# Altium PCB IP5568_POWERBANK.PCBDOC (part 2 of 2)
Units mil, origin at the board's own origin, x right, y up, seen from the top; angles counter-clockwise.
Board outline 4566.93 x 4566.93 mil, 4 copper layers (Top Layer, MID1, MID2, Bottom Layer), stack 38.627 mil thick; 85 components, 61 nets, 294 pads, 184 vias.
Unrouted connection lines stored in the file: 1.
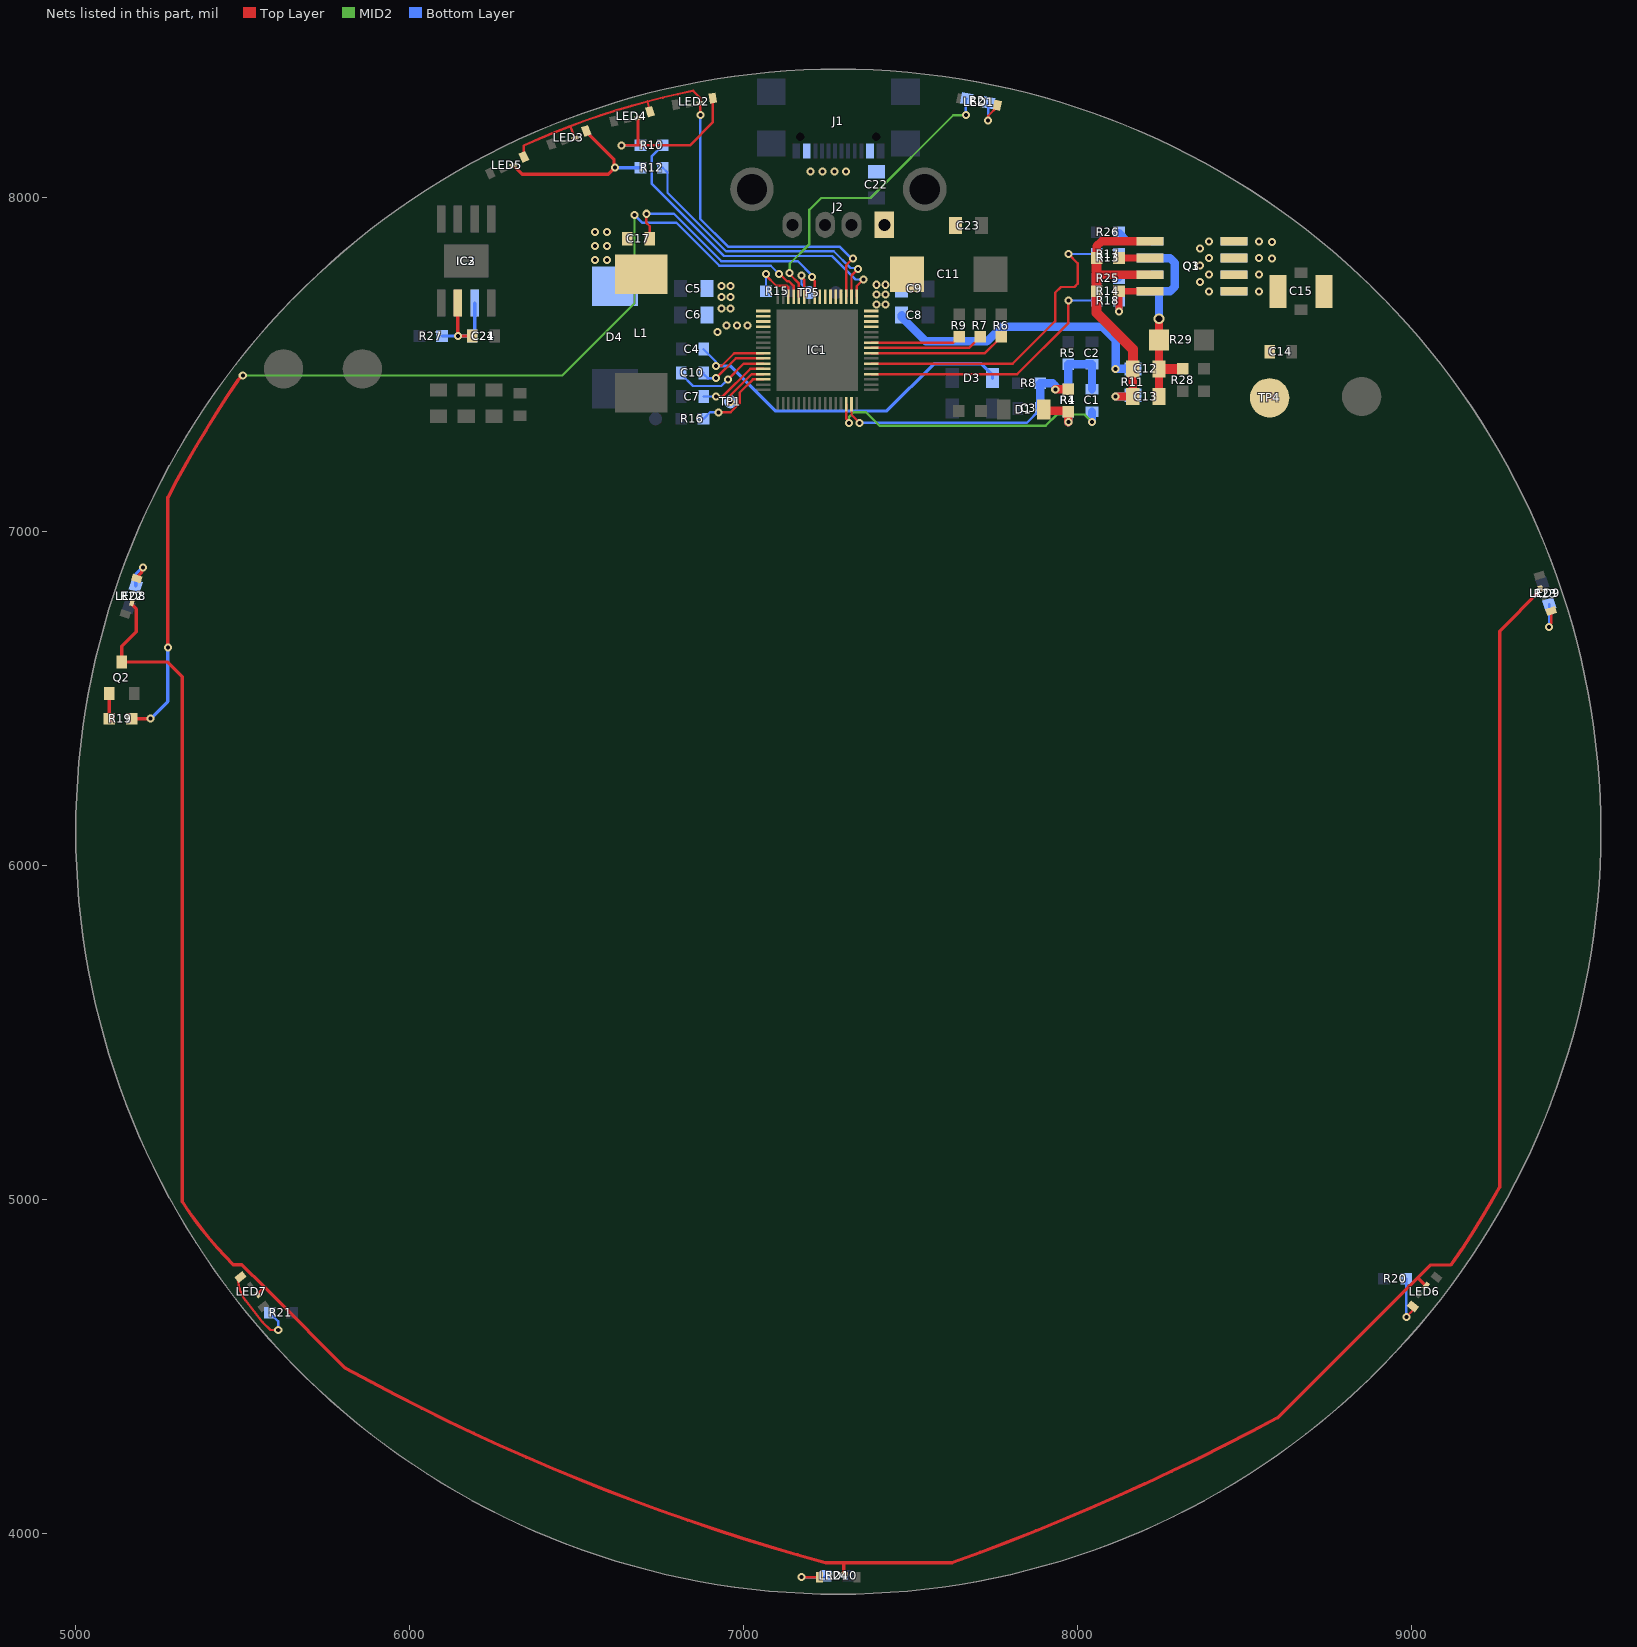
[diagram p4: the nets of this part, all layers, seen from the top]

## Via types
v1: diameter 24, hole 12, Top Layer to Bottom Layer, 166 vias
v2: diameter 32, hole 20, Top Layer to Bottom Layer, 18 vias

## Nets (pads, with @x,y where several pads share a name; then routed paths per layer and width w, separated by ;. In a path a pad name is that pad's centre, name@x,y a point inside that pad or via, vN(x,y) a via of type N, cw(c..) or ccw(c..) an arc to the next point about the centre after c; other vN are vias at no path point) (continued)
LED_G: LED6.3 LED7.3 LED8.3 LED9.3 LED10.3 Q2.3 | length 8606.9
  Top Layer w10: LED8.3@5168.42,6788.5 5168.42,6782.08 5181.1,6769.4 5181.1,6700.79 5137.8,6657.48 Q2.3@5137.8,6610.24 5275.59,6610.24 5318.9,6566.93 5318.9,4996.36 5318.9,4994.29 ccw(c6286.81,5620.98) 5471.46,4805.63 5474.36,4805.63 5497.52,4805.63 5565.64,4737.51 ; LED7.3@5544.69,4716.56 5565.64,4737.51 ; LED10.3@7300.2,3878.74 7300.2,3913.39 ; LED6.3@9043.17,4742.78 9018.96,4766.99 ; LED9.3@9387.17,6829.22 9387.17,6826.57 9263.78,6703.18 9263.78,5037.59 cw(c6837.52,6394.47) 9118.16,4804.95 9056.92,4804.95 9018.96,4766.99 ; 5565.64,4737.51 5586.59,4716.56 5805.71,4497.44 5806.41,4496.74 ccw(c8968.12,10228.09) 7244.96,3913.39 7245.89,3913.39 7300.2,3913.39 ; 7300.2,3913.39 7625.21,3913.39 ccw(c5102.66,10885.2) 8599.42,4347.46 9018.96,4766.99
NetC1_1: C1.1 C2.1 R1.1 R5.1 | length 220.5
  Bottom Layer w25: R1.1@7972.44,7427.17 R5.1@7972.44,7501.97 C2.1@8043.31,7501.97 C1.1@8043.31,7427.17
NetC7_2: C7.2 IC1.28 | length 213.4
  Top Layer w7: v1(6917.32,7405.51) 6936.89,7405.51 7019.57,7488.19 IC1.28@7059.06,7488.19
  Bottom Layer w7: C7.2@6879.92,7405.51 v1(6917.32,7405.51)
NetC10_1: C10.1 IC1.26 | length 212.2
  Top Layer w7: v1(6917.32,7460.63) 6976.38,7519.69 IC1.26@7059.06,7519.69
  Bottom Layer w7: C10.1@6879.92,7476.38 6879.92,7472.88 6892.17,7460.63 v1(6917.32,7460.63)
NetC10_2: C10.2 IC1.27 | length 292.4
  Top Layer w7: v1(6952.76,7456.69) 7000,7503.94 IC1.27@7059.06,7503.94
  Bottom Layer w7: C10.2@6812.99,7476.38 6812.99,7472.44 6848.43,7437.01 6933.07,7437.01 v1(6952.76,7456.69)
NetC12_2: C12.2 C13.2 Q3.1 Q3.3 R28.1 R29.1 | length 622
  Top Layer w25: v2(8243.52,7638.37) R29.1@8243.52,7574.8 8243.81,7574.52 8243.81,7405.8 C13.2@8244.09,7405.51 ; C12.2@8244.09,7488.19 C12.2@8247.05,7485.24
  Top Layer w30: C12.2@8244.09,7488.19 R28.1@8314.96,7488.19
  Bottom Layer w25: Q3.1@8216.77,7720.28 Q3.1@8243.23,7720.28 ; Q3.3@8216.77,7820.28 8217.07,7819.98 8276.69,7819.98 8291.34,7805.34 8291.34,7734.92 8276.69,7720.28 Q3.1@8243.23,7720.28 ; v2(8243.52,7638.37) 8243.52,7719.98 Q3.1@8243.23,7720.28
NetC14_2: C14.2 Q1.5 Q1.6 Q3.5 Q3.6 TP4.1
  other v1: 8393.7,7720.28 8366.14,7748.03 8393.7,7770.28 8366.14,7798.03 8393.7,7820.28 8366.14,7848.03 8393.7,7870.28
NetC15_A: C15.A C15.B Q1.7 Q1.8 Q3.7 Q3.8
  other v1: 8542.83,7720.28 8542.83,7770.28 8582.68,7818.9 8542.83,7820.28 8582.68,7868.9 8542.83,7870.28
NetC17_1: C17.1 IC1.9 | length 718
  Top Layer w7: v1(6708.66,7952.76) 6708.66,7925.2 6718.5,7915.35 C17.1@6718.5,7877.95 ; v1(7204.72,7763.78) 7204.72,7759.18 7212.6,7751.31 IC1.9@7212.6,7704.72
  Bottom Layer w7: v1(6708.66,7952.76) 6791.34,7952.76 6933.07,7811.02 7161.74,7811.02 7204.72,7768.04 v1(7204.72,7763.78)
NetC17_2: C17.2 D4.K IC1.4 IC1.5 IC1.6 IC1.7 IC1.8 L1.1
  other v1: 6555.12,7814.96 6590.55,7814.96 6555.12,7856.3 6590.55,7856.3 6555.12,7897.64 6590.55,7897.64
NetC21_1: C21.1 C24.1 IC2.6 IC3.6 R27.1 | length 333.6
  Top Layer w10: IC3.6@6144.29,7685.28 v1(6144.29,7586.61) C24.1@6187.01,7586.61
  Bottom Layer w10: R27.1@6096.46,7586.61 v1(6144.29,7586.61) C21.1@6187.01,7586.61 6194.29,7593.9 IC2.6@6194.29,7685.28
NetD1_K: D1.K R1.2 R4.2 | length 139.3
  Top Layer w25: D1.K@7898.58,7366.14 7901.54,7363.19 7969.49,7363.19 R4.2@7972.44,7360.24 v1(7972.44,7328.74)
  Bottom Layer w25: v1(7972.44,7328.74) R1.2@7972.44,7360.24
NetIC1_1: IC1.1 R10.1 | length 940.3
  Top Layer w7: IC1.1@7338.58,7704.72 7338.58,7736.22 v1(7358.27,7755.91)
  Bottom Layer w7: R10.1@6757.87,8157.48 6724.41,8124.02 6724.41,8043.31 6941.39,7826.33 7264.11,7826.33 7334.53,7755.91 v1(7358.27,7755.91)
NetIC1_2: IC1.2 R12.1 | length 836.7
  Top Layer w7: IC1.2@7322.83,7704.72 7322.83,7767.72 v1(7342.52,7787.4)
  Bottom Layer w7: R12.1@6757.87,8090.55 6771.87,8076.55 6771.87,8015.64 6947.18,7840.33 7269.91,7840.33 7320.02,7790.22 7339.7,7790.22 v1(7342.52,7787.4)
NetIC1_3: IC1.3 LED2.2 LED3.2 LED4.1 LED5.1 | length 1658.7
  Top Layer w7: LED5.1@6341.76,8123.02 6341.76,8157.04 cw(c7297.89,6061.85) 6480.86,8215.1 ; LED3.2@6495.1,8179.01 6480.86,8215.1 ; LED4.1@6719.55,8258.61 6712.14,8289.16 ; v1(6870.08,8248.03) 6869.72,8248.39 6869.72,8283.11 LED2.2@6870.08,8283.46 6870.08,8299.21 6851.29,8318 6848.64,8320.65 ccw(c7297.89,6061.85) 6712.14,8289.16 ; IC1.3@7307.09,7704.72 7307.09,7799.21 v1(7326.77,7818.9) ; 6480.86,8215.1 cw(c7297.89,6061.85) 6712.14,8289.16
  Bottom Layer w7: v1(6870.08,8248.03) 6870.08,7937.24 6952.98,7854.33 7287.05,7854.33 7322.49,7818.9 v1(7326.77,7818.9)
NetIC1_11: IC1.11 TP5.1 | length 127.2
  Top Layer w7: v1(7173.23,7767.72) 7173.23,7763.12 7181.1,7755.24 IC1.11@7181.1,7704.72
  Bottom Layer w7: v1(7173.23,7767.72) 7173.23,7742.11 7196.85,7718.48 TP5.1@7196.85,7716.54
NetIC1_12: IC1.12 R2.1 | length 931.8
  Top Layer w7: v1(7137.8,7775.59) 7137.8,7771.33 7165.35,7743.77 IC1.12@7165.35,7704.72
  MID2 w7: v1(7137.8,7775.59) 7137.8,7803.15 7196.85,7862.2 7196.85,7964.57 7232.28,8000 7379.86,8000 7627.89,8248.03 v1(7665.35,8248.03)
  Bottom Layer w7: v1(7665.35,8248.03) 7665.35,8294.67 R2.1@7667.83,8297.15
NetIC1_13: IC1.13 R19.2 | length 3293.1
  Top Layer w7: v1(7106.3,7771.65) 7108.87,7771.65 7129.64,7750.88 7135.49,7750.88 7149.61,7736.76 IC1.13@7149.61,7704.72
  Top Layer w10: R19.2@5167.32,6440.94 v1(5224.41,6440.94) ; v1(5275.59,6653.54) 5275.59,7103.53 cw(c8474.13,5425.33) 5485.72,7454.22 v1(5500,7468.5)
  MID2 w7: v1(5500,7468.5) 6456.69,7468.5 6673.23,7685.04 v1(6673.23,7948.82)
  Bottom Layer w7: v1(6673.23,7948.82) 6695.91,7926.14 6798.15,7926.14 6927.27,7797.02 7080.93,7797.02 v1(7106.3,7771.65)
  Bottom Layer w10: v1(5224.41,6440.94) 5275.59,6492.13 v1(5275.59,6653.54)
NetIC1_29: IC1.29 TP1.1 | length 144.2
  Top Layer w7: v1(6960.63,7389.76) 6960.63,7409.45 7023.62,7472.44 IC1.29@7059.06,7472.44
NetIC1_56: IC1.56 R6.1 | length 410.1
  Top Layer w7: IC1.56@7381.89,7535.43 7722.44,7535.43 R6.1@7771.65,7584.65
NetIC1_57: IC1.57 R7.1 | length 340.6
  Top Layer w7: IC1.57@7381.89,7551.18 7675.2,7551.18 R7.1@7708.66,7584.65
NetIC1_58: IC1.58 R9.1 | length 271.1
  Top Layer w7: IC1.58@7381.89,7566.93 7627.95,7566.93 R9.1@7645.67,7584.65
NetLED1_1: LED1.1 R2.2 | length 110.7
  Top Layer w7: v1(7732.28,8232.28) 7732.28,8246.3 7759.97,8273.99 LED1.1@7759.97,8277.66
  Bottom Layer w7: v1(7732.28,8232.28) 7732.28,8284.07 R2.2@7733.74,8285.53
NetLED2_1: LED2.1 LED4.2 R10.2 | length 514.2
  Top Layer w7.87: v1(6633.86,8157.48) 6683.76,8157.48 ; LED4.2@6683.76,8240.06 6683.76,8157.48 ; LED2.1@6907.35,8298.83 6907.35,8226.24 6838.58,8157.48 6683.76,8157.48
  Bottom Layer w7.87: v1(6633.86,8157.48) R10.2@6690.94,8157.48
NetLED3_1: LED3.1 LED5.2 R12.2 | length 546.2
  Top Layer w10: LED5.2@6310.17,8097.98 6337.28,8070.87 6594.49,8070.87 v1(6614.17,8090.55) 6611.49,8093.23 6611.49,8115.86 6528.75,8198.6 LED3.1@6528.75,8201.21
  Bottom Layer w10: v1(6614.17,8090.55) R12.2@6690.94,8090.55
NetLED6_1: LED6.1 R20.2 | length 153.5
  Top Layer w7: v1(8984.25,4649.61) 9004.06,4669.42 LED6.1@9004.06,4680.72
  Bottom Layer w7: v1(8984.25,4649.61) R20.2@8984.25,4763.78
NetLED7_1: LED7.1 R21.2 | length 278.7
  Top Layer w7: LED7.1@5493.02,4768.62 5488.63,4764.23 5486.54,4762.14 ccw(c5590.77,4762.14) 5507.8,4699.06 ccw(c7352.82,6100.39) 5559.77,4633.14 5560.02,4632.89 5582.68,4610.24 v1(5606.3,4610.24)
  Bottom Layer w7: R21.2@5580.71,4661.42 5606.3,4635.83 v1(5606.3,4610.24)
NetLED8_1: LED8.1 R22.2 | length 104.3
  Top Layer w10: LED8.1@5182.69,6860.44 5182.69,6864.98 5197.53,6879.82 5197.53,6890.45 v1(5200.79,6893.7)
  Bottom Layer w10: R22.2@5179.63,6838.91 5179.63,6872.55 v1(5200.79,6893.7)
NetLED9_1: LED9.1 R23.2 | length 118.1
  Top Layer w7: v1(9411.92,6715.07) 9411.92,6719.67 9417.91,6725.66 LED9.1@9417.91,6762.63
  Bottom Layer w7: v1(9411.92,6715.07) R23.2@9411.92,6783.13
NetLED10_1: LED10.1 R24.2 | length 128.6
  Top Layer w7: v1(7173.23,3870.08) LED10.1@7227.36,3870.08
  Bottom Layer w7: v1(7173.23,3870.08) 7242.13,3870.08 R24.2@7246.06,3874.02
NetQ1_2: Q1.2 R13.2 R17.1 | length 92.8
  Top Layer w20: R13.2@8124.02,7820.28 Q1.2@8216.77,7820.28
NetQ1_4: Q1.4 R14.2 R18.1 | length 187
  Top Layer w20: v1(8124.02,7659.45) R14.2@8124.02,7720.28 Q1.4@8216.77,7720.28
  Bottom Layer w20: v1(8124.02,7659.45) R18.1@8124.02,7692.91
NetQ2_1: Q2.1 R19.1 | length 74.8
  Top Layer w10: R19.1@5100.39,6440.94 Q2.1@5100.39,6515.75
NetQ3_2: Q3.2 R25.1 | length 97.1
  Bottom Layer w20: R25.1@8124.02,7759.84 8134.45,7770.28 Q3.2@8216.77,7770.28
NetQ3_4: Q3.4 R26.2 | length 104.1
  Bottom Layer w20: R26.2@8124.02,7897.64 8151.38,7870.28 Q3.4@8216.77,7870.28
NTC1: IC1.14 R15.1 | length 164.5
  Top Layer w7: v1(7066.93,7771.65) 7066.93,7767.72 7097.77,7736.88 7129.69,7736.88 7133.79,7732.78 7133.79,7704.79 IC1.14@7133.86,7704.72
  Bottom Layer w7: R15.1@7066.93,7720.47 v1(7066.93,7771.65)
NTC2: IC1.30 R16.1 | length 246.6
  Top Layer w7: v1(6925.2,7358.27) 6960.95,7358.27 6988.19,7385.5 6988.19,7417.21 7027.67,7456.69 IC1.30@7059.06,7456.69
  Bottom Layer w7: R16.1@6879.92,7338.58 6899.61,7358.27 v1(6925.2,7358.27)
UPGATE1: IC1.54 R17.2 | length 952.3
  Top Layer w7: IC1.54@7381.89,7503.94 7805.74,7503.94 7933.07,7631.27 7933.07,7716.54 7949.91,7733.37 7990.52,7733.37 8000,7742.85 8000,7804.53 v1(7972.44,7832.09)
  Bottom Layer w7: v1(7972.44,7832.09) R17.2@8057.09,7832.09
UPGATE2: IC1.52 R18.2 | length 805.7
  Top Layer w7: IC1.52@7381.89,7472.44 7818.9,7472.44 7972.44,7625.98 v1(7972.44,7692.91)
  Bottom Layer w7: v1(7972.44,7692.91) R18.2@8057.09,7692.91
V_DECODE: C1.2 IC1.46 | length 881.1
  Top Layer w7: IC1.46@7307.09,7381.89 7307.09,7339.25 7314.96,7331.37 v1(7314.96,7326.77)
  MID2 w7: v1(7314.96,7326.77) 7315.28,7327.09 7315.28,7344.27 7329.27,7358.27 7366.14,7358.27 7406.76,7317.65 7904.26,7317.65 7937.99,7351.38 8020.67,7351.38 v1(8043.31,7328.74)
  Bottom Layer w25: v1@8043.31,7329.15 C1.2@8043.31,7360.24
V_DET: C3.1 IC1.47 R4.1 R8.2 | length 803.3
  Top Layer w7: IC1.47@7322.83,7381.89 7322.83,7350.72 7346.46,7327.1 v1(7346.46,7326.77) ; v1@7928.81,7427.17 v1(7933.07,7427.17)
  Top Layer w25: v1(7933.07,7427.17) R4.1@7972.44,7427.17
  Bottom Layer w7: v1(7346.46,7326.77) 7848.43,7326.77 7887.8,7366.14 C3.1@7887.8,7370.08
  Bottom Layer w25: C3.1@7887.8,7370.08 R8.2@7887.8,7444.88 7925.2,7444.88 7933.07,7437.01 v1(7933.07,7427.17)
VBRIDGE: C12.1 C13.1 Q1.1 Q1.3 R11.1 R13.1 R14.1 | length 924.4
  Top Layer w25: 8057.09,7770.28 Q1.3@8216.77,7770.28 ; R13.1@8057.09,7820.28 8057.09,7855.63 8071.73,7870.28 Q1.1@8216.77,7870.28 ; v1(8114.17,7405.51) C13.1@8165.35,7405.51 C12.1@8165.35,7488.19
  Top Layer w30: R13.1@8057.09,7820.28 8057.09,7770.28 R14.1@8057.09,7720.28 8057.09,7655.51 8165.35,7547.24 C12.1@8165.35,7488.19
  Bottom Layer w25: v1(8114.17,7405.51) 8161.42,7405.51 R11.1@8165.35,7409.45
VBUS: C22.1 IC1.19 IC1.20 J1.A4/B9 J1.B4/A9
  other v1: 6921.26,7598.43 6948.82,7618.11 6980.31,7618.11 7011.81,7618.11 7200.79,8078.74 7236.22,8078.74 7271.65,8078.74 7307.09,8078.74
VCC: C4.2 D3.K IC1.25 | length 1189.4
  Top Layer w7: v1(6917.32,7497.05) 6917.92,7497.65 6934.54,7497.65 6970.58,7533.69 6970.69,7533.69 6972.44,7535.43 IC1.25@7059.06,7535.43
  Bottom Layer w7: C4.2@6879.92,7547.24 6917.32,7509.84 v1(6917.32,7497.05)
  Bottom Layer w10: v1(6917.32,7497.05) 6959.65,7497.05 7094.49,7362.2 7429.13,7362.2 7570.87,7503.94 7711.73,7503.94 7745.04,7470.63 D3.K@7745.04,7460.63
VOUT1: C23.1 IC1.61 IC1.62 J2.1
VSYS: C5.1 C6.1 C8.1 C9.1 C11.1 IC1.17 IC1.18 IC1.63 IC1.64 R11.2 | length 849
  Bottom Layer w25: C8.1@7473.12,7649.3 7473.12,7643.39 7545.64,7570.87 7728.35,7570.87 7771.65,7614.17 8074.8,7614.17 8114.17,7574.8 v1(8114.17,7488.19) R11.2@8165.35,7488.19
  other v1: 6933.07,7669.29 6960.63,7669.29 7397.64,7681.1 7425.2,7681.1 6933.07,7702.76 6960.63,7702.76 7397.64,7710.63 7425.2,7710.63 6933.07,7736.22 6960.63,7736.22 7397.64,7740.16 7425.2,7740.16
pads on no net: IC1.15 IC1.16 IC1.21 IC1.22 IC1.31 IC1.36 IC1.37 IC1.38 IC1.41 IC1.42 IC1.49 IC1.50 IC1.51 IC1.59 IC1.60 J1. J1.A8 J1.B8 LED1.2 LED1.3 LED2.3 LED2.4 LED3.3 LED3.4 LED4.3 LED4.4 LED5.3 LED5.4 LED6.2 LED6.4 LED7.2 LED7.4 LED8.2 LED8.4 LED9.2 LED9.4 LED10.2 LED10.4

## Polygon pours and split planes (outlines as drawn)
GND on Top Layer "GND_L01_P024" (solid, remove dead copper, pour order 24): 4960.63,8425.2 9645.67,8425.2 9645.67,3740.16 4960.63,3740.16
BAT- on Top Layer "BAT-_L01_P019" (solid, remove dead copper, pour order 19): 5511.81,7381.89 5511.81,7566.93 5807.09,7862.2 6248.03,7862.2 6259.84,7850.39 6259.84,7637.8 5826.77,7637.8 5728.35,7539.37 5728.35,7381.89
BAT+ on Top Layer "Top Layer-BAT+" (solid, remove dead copper, pour order 18): 6594.49,7358.27 6791.34,7358.27 6791.34,7421.26 6917.32,7547.24 7082.68,7547.24 7082.68,7570.87 6610.24,7570.87 6539.37,7500 6062.99,7500 5984.25,7578.74 5826.77,7578.74 5767.72,7519.68 5767.72,7381.89 6570.87,7381.89
VBUS on Top Layer "VBUS_L01_P012" (solid, remove dead copper, pour order 12): 7003.72,7582.68 7030.4,7609.36 7082.68,7609.36 7082.68,7633.86 6913.39,7633.86 6905.51,7625.98 6905.51,7590.55 6913.39,7582.68 6937.01,7582.68
COIL_V on Top Layer "COIL_V_L01_P011" (solid, remove dead copper, pour order 11): 8956.69,7303.15 8956.69,7539.37 8838.58,7657.48 8712.6,7657.48 8700.79,7669.29 8700.79,7791.34 8696.85,7795.28 8641.73,7795.28 8637.8,7791.34 8637.8,7637.8 8618.11,7618.11 8618.11,7523.62 8720.47,7421.26 8720.47,7303.15
NetC15_A on Top Layer "NETC15_A_L01_P010" (solid, remove dead copper, pour order 10): 8633.86,7803.15 8629.92,7799.21 8629.92,7673.23 8625.98,7669.29 8562.99,7669.29 8527.56,7704.72 8527.56,7799.21 8523.62,7803.15 8429.13,7803.15 8425.2,7807.09 8425.2,7885.83 8433.07,7893.7 8712.6,7893.7 8767.72,7838.58 8767.72,7669.29 8763.78,7665.35 8716.54,7665.35 8708.66,7673.23 8708.66,7795.28 8700.79,7803.15
NetC14_2 on Top Layer "NETC14_2_L01_P007" (solid, remove dead copper, pour order 7): 8484.25,7303.15 8484.25,7559.06 8346.46,7696.85 8346.46,7885.83 8354.33,7893.7 8409.45,7893.7 8413.39,7889.76 8413.39,7799.21 8417.32,7795.28 8507.87,7795.28 8515.75,7787.4 8515.75,7685.04 8602.36,7598.43 8602.36,7519.69 8661.42,7460.63 8661.42,7303.15
VOUT1 on Top Layer "VOUT1_L01_P006" (solid, remove dead copper, pour order 6): 7358.27,7633.86 7476.38,7633.86 7559.06,7716.54 7559.06,7838.58 7543.31,7854.33 7381.89,7854.33 7381.89,7972.44 7637.8,7972.44 7665.35,7944.88 7665.35,7720.47 7555.12,7610.24 7358.27,7610.24
VSYS on Top Layer "VSYS_L01_P002" (solid, remove dead copper, pour order 2): 7381.89,7771.65 7437.01,7826.77 7539.37,7826.77 7543.31,7822.83 7543.31,7720.47 7464.57,7641.73 7358.27,7641.73 7358.27,7669.29 7381.89,7692.91
VSYS on Top Layer "VSYS_L01_P001" (solid, remove dead copper, pour order 1): 7082.68,7641.73 6929.13,7641.73 6917.32,7653.54 6917.32,7748.03 6921.26,7751.97 6972.44,7751.97 6976.38,7748.03 6976.38,7688.98 6992.13,7673.23 7082.68,7673.23
NetC17_2 on Top Layer "NETC17_2_L01_P000" (solid, remove dead copper, pour order 0): 6562.99,7708.66 6535.43,7736.22 6535.43,7901.57 6547.24,7913.39 6665.35,7913.39 6673.23,7905.51 6673.23,7873.8 6695.76,7851.27 6741.25,7851.27 6763.78,7874.02 7283.46,7874.02 7295.28,7862.2 7295.28,7681.1 7224.41,7681.1 7224.41,7779.53 7212.6,7791.34 6866.14,7791.34 6783.46,7708.66
GND on Bottom Layer "GND_L04_P023" (solid, remove dead copper, pour order 23): 4960.63,8425.2 9645.67,8425.2 9645.67,3740.16 4960.63,3740.16
BAT- on Bottom Layer "BAT-_L04_P020" (solid, remove dead copper, pour order 20): 6279.53,7854.33 6271.65,7862.2 6070.87,7862.2 6062.99,7854.33 6062.99,7629.92 6074.8,7618.11 6267.72,7618.11 6279.53,7629.92
VBUS on Bottom Layer "VBUS_L04_P015" (solid, remove dead copper, pour order 15): 7421.26,8102.36 7429.1,8094.53 7429.13,8059.06 7421.26,8051.18 7188.98,8051.18 7177.17,8062.99 7177.17,8165.35 7200.79,8165.35 7200.79,8106.3 7208.66,8098.43 7358.27,8098.42 7366.14,8106.3 7366.14,8165.35 7389.76,8165.35 7389.76,8110.24 7397.64,8102.36
NetC17_2 on Bottom Layer "NETC17_2_L04_P013" (solid, remove dead copper, pour order 13): 6535.43,7669.29 6547.24,7657.48 6681.1,7657.48 6692.91,7669.29 6692.91,7901.57 6681.1,7913.39 6543.31,7913.39 6535.43,7905.51
VSYS on Bottom Layer "VSYS_L04_P005" (solid, remove dead copper, pour order 5): 6917.32,7618.11 6925.2,7625.98 6925.2,7645.67 6933.07,7653.54 6968.5,7653.54 6976.38,7661.42 6976.38,7748.03 6968.5,7755.91 6862.2,7755.91 6854.33,7748.03 6854.33,7625.98 6862.2,7618.11
NetC15_A on Bottom Layer "NETC15_A_L04_P009" (solid, remove dead copper, pour order 9): 8429.13,7787.4 8421.26,7779.53 8421.26,7708.66 8429.13,7700.79 8562.99,7700.79 8602.36,7740.16 8602.36,7885.83 8594.49,7893.7 8535.43,7893.7 8527.56,7885.83 8527.56,7799.21 8515.75,7787.4
NetC14_2 on Bottom Layer "NETC14_2_L04_P008" (solid, remove dead copper, pour order 8): 8507.87,7893.7 8354.33,7893.7 8346.46,7885.83 8346.46,7708.66 8354.33,7700.79 8401.57,7700.79 8413.39,7712.6 8413.39,7787.4 8421.26,7795.28 8507.87,7795.28 8515.75,7803.15 8515.75,7885.83
VSYS on Bottom Layer "VSYS_L04_P004" (solid, remove dead copper, pour order 4): 7496.06,7755.91 7389.76,7755.91 7381.89,7748.03 7381.89,7622.05 7389.76,7614.17 7496.06,7614.17 7503.94,7622.05 7503.94,7748.03
GND on MID2 "GND_L03_P026" (solid, remove dead copper, pour order 26): 4960.63,8425.2 9645.67,8425.2 9645.67,3740.16 4960.63,3740.16
VBUS on MID2 "VBUS_L03_P022" (solid, remove dead copper, pour order 22): 7027.56,7625.98 7019.69,7633.86 6909.45,7633.86 6889.76,7653.54 6889.76,8031.5 6956.69,8098.42 7078.74,8098.42 7122.05,8055.12 7318.9,8055.12 7330.71,8066.93 7330.71,8157.48 7318.9,8169.29 6889.76,8169.29 6811.02,8090.55 6811.02,7618.11 6850.39,7578.74 7019.69,7578.74 7027.56,7586.61
VSYS on MID2 "VSYS_L03_P021" (solid, remove dead copper, pour order 21): 6913.39,7755.9 6913.39,7649.61 7090.55,7649.61 7106.3,7665.35 7440.94,7665.35 7440.94,7755.91
GND on MID1 "GND_L02_P025" (solid, remove dead copper, pour order 25): 4960.63,8425.2 9645.67,8425.2 9645.67,3740.16 4960.63,3740.16

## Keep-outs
Keep-Out Layer:
  lines w8: 5000,6102.36 cw(c7321.08,6102.46) 5002.92,6218.94 cw(c7283.98,6102.07) 7004.07,8368.91 cw(c7282.07,6089.07) 7163.16,8382.71 cw(c7283.36,6065.11) 7283.46,8385.83 cw(c7283.57,6064.73) 7400.04,8382.9 cw(c7283.18,6101.85) 9550.01,6381.76 cw(c7270.17,6103.75) 9563.81,6222.67 cw(c7246.21,6102.47) 9566.93,6102.36 cw(c7245.84,6102.26) 9564.01,5985.79 cw(c7282.95,6102.65) 7562.86,3835.82 cw(c7284.86,6115.66) 7403.77,3822.01 cw(c7283.57,6139.62) 7283.46,3818.9 cw(c7283.36,6139.98) 7166.89,3821.82 cw(c7283.76,6102.88) 5016.92,5822.97 cw(c7296.76,6100.97) 5003.11,5982.05 cw(c7320.71,6102.25) 5000,6102.36 ; 5078.74,6200.79 ccw(c5178.79,6200.78) 5078.86,6195.76 ccw(c5177.19,6200.8) 5165.12,6103.09 ccw(c5177.1,6201.36) 5171.98,6102.5 ccw(c5177.16,6202.39) 5177.16,6102.36 ccw(c5177.17,6202.41) 5182.19,6102.49 ccw(c5177.15,6200.81) 5274.86,6188.75 ccw(c5176.59,6200.73) 5275.46,6195.6 ccw(c5175.56,6200.78) 5275.59,6200.79 ccw(c5175.55,6200.79) 5275.46,6205.81 ccw(c5177.14,6200.77) 5189.21,6298.48 ccw(c5177.22,6200.22) 5182.35,6299.08 ccw(c5177.17,6199.18) 5177.16,6299.21 ccw(c5177.16,6199.17) 5172.14,6299.09 ccw(c5177.18,6200.76) 5079.47,6212.83 ccw(c5177.73,6200.85) 5078.87,6205.97 ccw(c5178.77,6200.79) 5078.74,6200.79 ; 5354.33,5034.48 5355.55,5032.28 ccw(c7312.75,6120.85) 5386.4,4978.57 ccw(c7293.45,6109.41) 5418.56,4926.02 ccw(c7274.65,6097.54) 5452.27,4874.25 ccw(c7256.34,6085.25) 5487.82,4822.89 5487.92,4822.84 9079.02,4822.84 9079.07,4822.84 9080.81,4825.28 ccw(c7308.61,6086.55) 9116.03,4876.28 ccw(c7290.5,6098.69) 9149.55,4927.9 ccw(c7271.84,6110.43) 9181.67,4980.5 ccw(c7252.63,6121.8) 9212.6,5034.48 9212.6,7170.25 9207.76,7178.93 ccw(c7275.49,6095.67) 9171.92,7240.51 ccw(c7294.52,6107.16) 9132.65,7303.15 5925.31,7303.15 5925.31,7381.89 5487.91,7381.89 5487.83,7381.85 ccw(c7256.69,6119.24) 5453.81,7332.77 ccw(c7274.23,6107.44) 5419.37,7279.98 ccw(c7292.84,6095.68) 5386.28,7225.94 ccw(c7312.02,6084.31) 5354.33,7170.25 5354.33,5034.48 ; 7145.67,4446.33 ccw(c7285.74,4446.33) 7145.85,4439.3 ccw(c7283.5,4446.35) 7266.61,4309.56 ccw(c7283.39,4447.14) 7276.21,4308.73 ccw(c7283.46,4448.59) 7283.47,4308.54 ccw(c7283.48,4448.6) 7290.51,4308.72 ccw(c7283.45,4446.36) 7420.24,4429.47 ccw(c7282.67,4446.25) 7421.08,4439.07 ccw(c7281.22,4446.33) 7421.26,4446.33 ccw(c7281.2,4446.34) 7421.09,4453.37 ccw(c7283.44,4446.32) 7300.33,4583.11 ccw(c7283.56,4445.54) 7290.73,4583.94 ccw(c7283.48,4444.09) 7283.47,4584.13 ccw(c7283.47,4444.06) 7276.44,4583.95 ccw(c7283.49,4446.3) 7146.7,4463.19 ccw(c7284.27,4446.42) 7145.86,4453.59 ccw(c7285.72,4446.34) 7145.67,4446.33 ; 9291.34,6200.79 ccw(c9391.39,6200.78) 9291.46,6195.76 ccw(c9389.79,6200.8) 9377.72,6103.09 ccw(c9389.7,6201.36) 9384.58,6102.5 ccw(c9389.76,6202.39) 9389.76,6102.36 ccw(c9389.77,6202.41) 9394.79,6102.49 ccw(c9389.75,6200.81) 9487.46,6188.75 ccw(c9389.19,6200.73) 9488.06,6195.6 ccw(c9388.16,6200.78) 9488.19,6200.79 ccw(c9388.15,6200.79) 9488.06,6205.81 ccw(c9389.74,6200.77) 9401.81,6298.48 ccw(c9389.82,6200.22) 9394.95,6299.08 ccw(c9389.77,6199.18) 9389.76,6299.21 ccw(c9389.76,6199.17) 9384.74,6299.09 ccw(c9389.78,6200.76) 9292.07,6212.83 ccw(c9390.33,6200.85) 9291.47,6205.97 ccw(c9391.37,6200.79) 9291.34,6200.79

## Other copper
Top Layer:
  pour cut-out: 6210.76,7558.93 6232.28,7558.93 6232.28,7574.68 6210.76,7574.68
  pour cut-out: 7244.09,7967.28 7374.02,7967.28 7374.02,7951.53 7244.09,7951.53
Bottom Layer:
  pour cut-out: 9395.53,6821.03 9395.53,6799.51 9379.78,6799.51 9379.78,6821.03
  pour cut-out: 7322.83,7834.65 7322.83,7965.99 7244.09,7965.99 7244.09,7834.65
  pour cut-out: 8196.85,7734.34 8196.85,7872.14 8098.52,7872.14 8098.52,7734.34
  pour cut-out: 6236.22,7576.86 6022.77,7576.86 6022.77,7559.06 6236.22,7559.06
  pour cut-out: 6767.63,8110.45 6767.63,8131.98 6783.37,8131.98 6783.37,8110.45
  pour cut-out: 6732.19,8161.45 6732.19,8182.98 6716.44,8182.98 6716.44,8161.45
  pour cut-out: 6681.19,8110.45 6681.19,8131.98 6665.44,8131.98 6665.44,8110.45
  pour cut-out: 6871.92,7498.03 6871.92,7622.05 6856.17,7622.05 6856.17,7498.03
  pour cut-out: 6815.21,7488.31 6856.17,7488.31 6856.17,7504.06 6815.21,7504.06
  pour cut-out: 8066.93,7421.39 8131.76,7421.39 8131.76,7437.13 8066.93,7437.13

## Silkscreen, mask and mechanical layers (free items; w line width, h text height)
Top Overlay:
  drawing of 4140 lines, arcs and shapes, not listed
  text "B-" at 5775.28,7610.55 h80 r90
  text "B+" at 5920.94,7610.55 h80 r90
  text "COIL" at 8712.91,7543.62 h80
Bottom Overlay:
  lines w8: 7220.47,7736.22 7232.28,7748.03 7232.28,7799.21 7220.47,7811.02
  text "GND" at 7295.91,7868.96 h40 r90
  text "LED_R" at 7212.47,7825.69 h40
  text "GND" at 6677.04,7322.96 h40
  text "KEY" at 7039.24,7315.09 h40
Bottom Solder:
  rectangle: 7098.43,7377.95 7370.08,7665.35
  region: 7362.2,7598.43 7480.32,7598.43 7535.43,7543.31 7535.43,7496.06 7417.32,7377.95 7362.2,7377.95
Mechanical 16:
  lines w5: 0,2775 200,2775 ; 0,5550 200,5550 ; 0,8325 200,8325 ; 1940,0 1940,200 ; 1940,10900 1940,11100 ; 3875,0 3875,200 ; 3875,10900 3875,11100 ; 5810,0 5810,200 ; 5810,10900 5810,11100 ; 7750,0 7750,200 ; 7750,10900 7750,11100 ; 9400,200 10800,200 ; 9685,0 9685,200 ; 9685,10900 9685,11100 ; 10800,500 15300,500 ; 10800,800 15300,800 ; 10800,1100 12300,1100 ; 11620,0 11620,200 ; 11620,10900 11620,11100 ; 12300,200 12300,800 12300,1400 ; 13560,0 13560,200 ; 13560,10900 13560,11100 ; 14400,200 14400,800 ; 15300,2775 15500,2775 ; 15300,5550 15500,5550 ; 15300,8325 15500,8325 ; 10800,200 15300,200 ; 10800,200 10800,1400 12300,1400 ; 12300,1400 15300,1400 15300,200 ; 15300,200 200,200 200,10900 15300,10900 15300,200 ; 0,0 0,11100 15500,11100 15500,0 0,0
  text "1" at 946.34,10965 h70
  text "2" at 2877,10965 h70
  text "3" at 4816.34,10965 h70
  text "4" at 6757,10965 h70
  text "5" at 8697,10965 h70
  text "6" at 10627,10965 h70
  text "7" at 12577,10965 h70
  text "8" at 14507,10965 h70
  text "A" at 75,9627 h70
  text "A" at 15375,9627 h70
  text "B" at 75,6847 h70
  text "B" at 15375,6847 h70
  text "C" at 75,4067 h70
  text "C" at 15375,4067 h70
  text "D" at 75,1307 h70
  text "D" at 15375,1307 h70
  text "ENGINEER:" at 10850,1300 h45
  text "TITLE:" at 12350,1300 h45
  text "PCB DESIGNER:" at 10850,1005 h45
  text "DATE:" at 10850,700 h45
  text "PART NO.:" at 12350,700 h45
  text "REV:" at 14450,700 h45
  text ".PRINT_DATE" at 10900,580 h70
  text "FILE NAME:" at 10850,400 h45
  text "DWG NO:" at 12350,400 h45
  text "SCALE:" at 14450,400 h45
  text ".PCB_FILE_NAME_NO_PATH" at 10900,280 h70
  text "1" at 946.34,65 h70
  text "2" at 2877,65 h70
  text "3" at 4816.34,65 h70
  text "4" at 6757,65 h70
  text "5" at 8697,65 h70
  text "6" at 10627,65 h70
  text "7" at 12577,65 h70
  text "8" at 14507,65 h70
